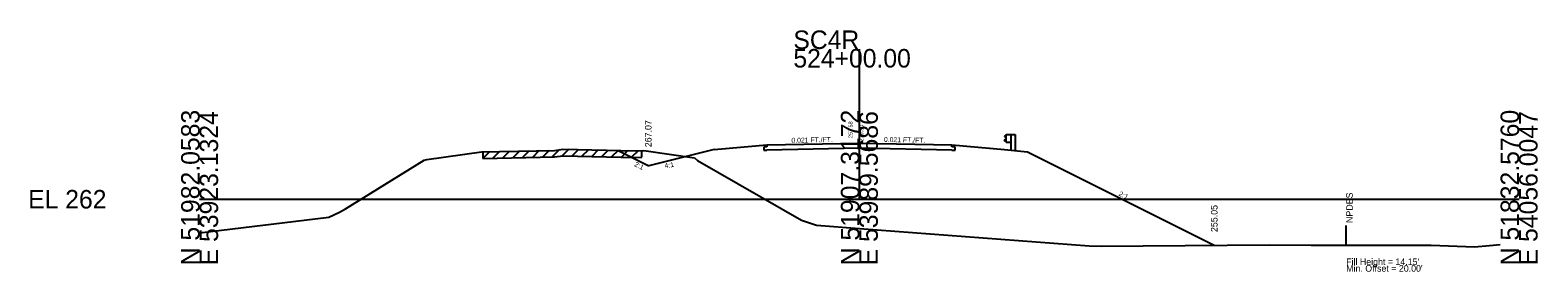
# Model space of a CAD drawing. Extents: x 7498 to 13027, y 90095 to 109625.
# Drawn here: x 9498.3 to 9726.8, y 94094.2 to 94130.7 of the extents above; entities that cross this region are included whole.
import ezdxf

# ---------------------------------------------------------------- set-up
doc = ezdxf.new("R2010")
doc.units = 0
for name, color, linetype in [('Level 10', 7, 'Continuous'), ('Level 11', 7, 'Continuous'), ('Level 12', 7, 'Continuous'), ('Level 24', 7, 'Continuous'), ('Level 32', 7, 'Continuous'), ('Level 33', 7, 'Continuous'), ('Level 50', 7, 'Continuous'), ('Level 55', 7, 'Continuous'), ('Level 59', 7, 'Continuous'), ('Level 6', 7, 'Continuous'), ('Level 60', 7, 'Continuous'), ('Level 61', 7, 'Continuous'), ('Level 63', 7, 'Continuous'), ('Level 7', 7, 'Continuous')]:
    doc.layers.add(name, color=color, linetype=linetype)

msp = doc.modelspace()

# ---------------------------------------------------------------- linework, layer by layer
at = {"layer": 'Level 11'}
for p, q in [((9609.99, 94113.07), (9609.49, 94113.05)), ((9609.49, 94113.05), (9609.49, 94112.57)), ((9609.49, 94112.57), (9609.99, 94112.59)), ((9609.99, 94113.37), (9609.99, 94113.07)), ((9637.99, 94113.07), (9637.99, 94113.37)), ((9638.49, 94113.05), (9637.99, 94113.07)), ((9637.99, 94112.59), (9638.49, 94112.57)), ((9638.49, 94112.57), (9638.49, 94113.05))]:
    msp.add_line(p, q, dxfattribs=at)
at = {"layer": 'Level 12'}
for p, q in [((9623.99, 94112.88), (9609.99, 94112.59)), ((9637.99, 94112.59), (9623.99, 94112.88))]:
    msp.add_line(p, q, dxfattribs=at)
at = {"layer": 'Level 24'}
for p, q in [((9646.26, 94114.88), (9645.99, 94114.68)), ((9645.99, 94114.68), (9645.99, 94114.63)), ((9645.99, 94114.63), (9646.26, 94114.43)), ((9645.99, 94114.1), (9646.26, 94114.3)), ((9645.99, 94114.05), (9645.99, 94114.1)), ((9646.26, 94113.85), (9645.99, 94114.05)), ((9646.26, 94113.78), (9646.26, 94114.95)), ((9646.26, 94114.95), (9646.93, 94114.95)), ((9646.93, 94114.95), (9646.93, 94112.6)), ((9646.93, 94114.95), (9647.6, 94114.95)), ((9647.6, 94114.95), (9647.6, 94112.54)), ((9646.26, 94113.78), (9646.93, 94113.78))]:
    msp.add_line(p, q, dxfattribs=at)
at = {"layer": 'Level 55'}
msp.add_line((9697.78, 94098.2), (9697.78, 94101.2), dxfattribs=at)
at = {"layer": 'Level 59'}
for p, q in [((9609.99, 94113.37), (9623.99, 94113.66)), ((9623.99, 94113.66), (9637.99, 94113.37))]:
    msp.add_line(p, q, dxfattribs=at)
at = {"layer": 'Level 6'}
for p, q in [((9601.99, 94112.7), (9609.99, 94113.37)), ((9637.99, 94113.37), (9645.99, 94112.7)), ((9645.99, 94112.7), (9649.49, 94112.35))]:
    msp.add_line(p, q, dxfattribs=at)
at = {"layer": 'Level 60'}
for p, q in [((9558.41, 94111.18), (9566.7, 94112.33)), ((9566.7, 94112.33), (9577.76, 94112.55)), ((9577.76, 94112.55), (9579.05, 94112.73)), ((9579.05, 94112.73), (9590.08, 94112.49)), ((9590.08, 94112.49), (9591.32, 94112.53)), ((9591.32, 94112.53), (9599.02, 94111.42)), ((9546.09, 94103.73), (9558.05, 94111.09)), ((9558.05, 94111.09), (9558.41, 94111.18)), ((9599.02, 94111.42), (9599.47, 94111.04)), ((9599.47, 94111.04), (9615.2, 94101.97)), ((9543.19, 94102.38), (9543.58, 94102.43)), ((9543.58, 94102.43), (9545.18, 94103.18)), ((9545.18, 94103.18), (9546.09, 94103.73)), ((9523.99, 94100.08), (9543.19, 94102.38)), ((9615.2, 94101.97), (9617.47, 94101.23)), ((9617.47, 94101.23), (9623.99, 94100.73)), ((9623.99, 94100.73), (9658.83, 94098.09)), ((9658.83, 94098.09), (9660.65, 94098.08)), ((9660.65, 94098.08), (9686.12, 94098.26)), ((9686.12, 94098.26), (9692.47, 94098.22)), ((9692.47, 94098.22), (9710.67, 94098.21)), ((9710.67, 94098.21), (9717.24, 94097.98)), ((9717.24, 94097.98), (9719.5, 94098.16)), ((9719.5, 94098.16), (9721.14, 94098.33))]:
    msp.add_line(p, q, dxfattribs=at)
at = {"layer": 'Level 61'}
for p, q in [((9567.96, 94112.36), (9566.94, 94111.34)), ((9566.94, 94112.34), (9566.94, 94111.34)), ((9566.94, 94111.34), (9577.76, 94111.55)), ((9569.46, 94112.39), (9568.44, 94111.37)), ((9570.96, 94112.42), (9569.94, 94111.4)), ((9572.46, 94112.45), (9571.44, 94111.43)), ((9573.96, 94112.48), (9572.94, 94111.46)), ((9575.46, 94112.51), (9574.44, 94111.49)), ((9576.96, 94112.54), (9575.94, 94111.52)), ((9578.56, 94112.66), (9577.44, 94111.55)), ((9577.76, 94111.55), (9579.05, 94111.73)), ((9579.94, 94112.71), (9578.94, 94111.72)), ((9579.05, 94111.73), (9590.08, 94111.49)), ((9581.42, 94112.68), (9580.44, 94111.7)), ((9582.92, 94112.65), (9581.94, 94111.67)), ((9584.42, 94112.61), (9583.44, 94111.63)), ((9585.92, 94112.58), (9584.94, 94111.6)), ((9587.42, 94112.55), (9586.44, 94111.57)), ((9588.92, 94112.51), (9587.94, 94111.54)), ((9590.44, 94112.5), (9589.44, 94111.5)), ((9591, 94111.52), (9591, 94112.52)), ((9590.08, 94111.49), (9591, 94111.52))]:
    msp.add_line(p, q, dxfattribs=at)
at = {"layer": 'Level 63'}
for p, q in [((9623.99, 94105.16), (9623.99, 94127.88)), ((9523.99, 94105.16), (9623.99, 94105.16)), ((9623.99, 94105.16), (9723.99, 94105.16))]:
    msp.add_line(p, q, dxfattribs=at)
at = {"layer": 'Level 7'}
for p, q in [((9587.44, 94112.55), (9592.09, 94110.22)), ((9601.99, 94112.7), (9592.09, 94110.22)), ((9649.49, 94112.35), (9677.79, 94098.2))]:
    msp.add_line(p, q, dxfattribs=at)

# ---------------------------------------------------------------- texts
at = {"layer": 'Level 10'}
msp.add_text('257.58', height=0.6, rotation=90, dxfattribs=at).set_placement((9622.95, 94114.4))
at = {"layer": 'Level 32'}
for s, rotation, p in [('0.021 FT./FT.', 1.1916, (9613.7, 94113.69)), ('0.021 FT./FT.', 358.8084, (9627.71, 94113.83)), ('2:1', 333.435, (9589.8, 94110.21)), ('4:1', 9.4623, (9594.52, 94109.83)), ('2:1', 333.435, (9663.24, 94105.75))]:
    msp.add_text(s, height=0.75, rotation=rotation, dxfattribs=at).set_placement(p)
at = {"layer": 'Level 33'}
for s, p in [('267.07', (9592.49, 94113.03)), ('255.05', (9678.28, 94100.2))]:
    msp.add_text(s, height=1, rotation=90, dxfattribs=at).set_placement(p)
at = {"layer": 'Level 50'}
msp.add_text(' NPDES', height=1, rotation=90, dxfattribs=at).set_placement((9698.78, 94101.2))
for s, p in [("Fill Height = 14.15' ", (9697.78, 94095.2)), ("Min. Offset = 20.00' ", (9697.78, 94094.2))]:
    msp.add_text(s, height=1, dxfattribs=at).set_placement(p)
at = {"layer": 'Level 59'}
msp.add_text(' 270.50', height=0.6, rotation=90, dxfattribs=at).set_placement((9624.59, 94113.66))
at = {"layer": 'Level 63'}
for s, p in [('SC4R', (9613.99, 94127.88)), ('524+00.00', (9613.99, 94125.08)), ('EL 262', (9498, 94103.76))]:
    msp.add_text(s, height=2.8, dxfattribs=at).set_placement(p)
for s, p in [('N 51982.0583', (9523.99, 94095.16)), ('N 51907.3172', (9623.99, 94095.16)), ('N 51832.5760', (9723.99, 94095.16)), ('E 53923.1324', (9526.79, 94095.16)), ('E 53989.5686', (9626.79, 94095.16)), ('E 54056.0047', (9726.79, 94095.16))]:
    msp.add_text(s, height=2.8, rotation=90, dxfattribs=at).set_placement(p)

doc.saveas('drawing.dxf')
